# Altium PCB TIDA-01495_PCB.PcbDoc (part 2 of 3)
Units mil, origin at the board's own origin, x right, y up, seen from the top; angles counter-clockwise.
Board outline 7283.46 x 4330.71 mil, 2 copper layers (Top Layer, Bottom Layer), stack 64.6 mil thick; 242 components, 114 nets, 539 pads, 127 vias.
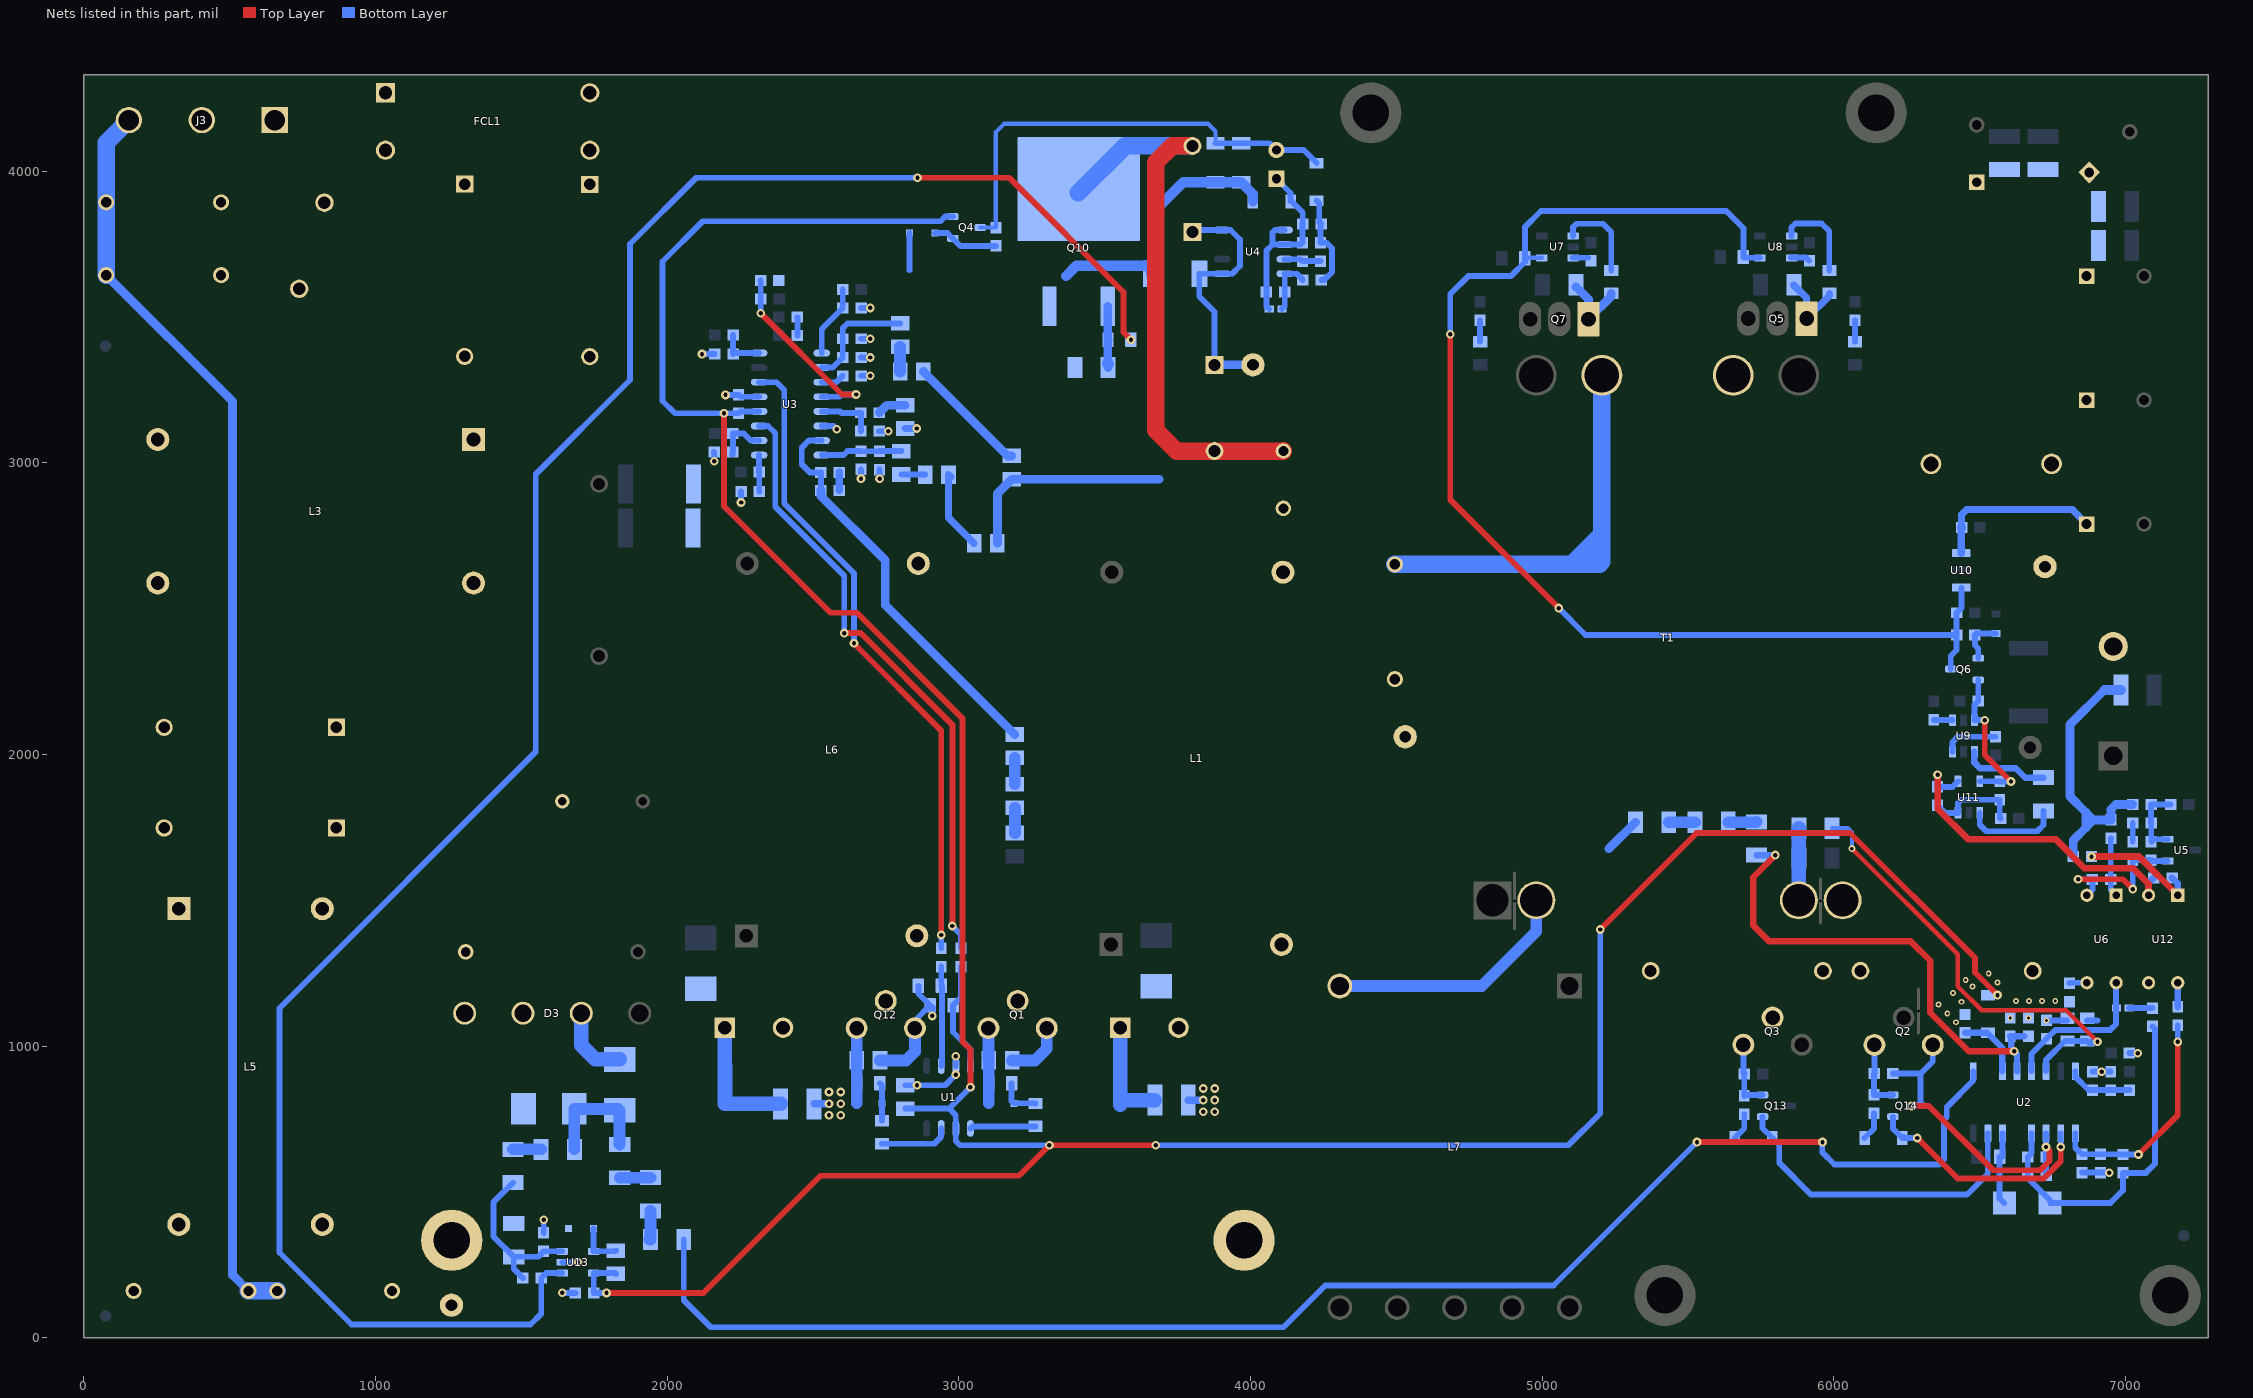
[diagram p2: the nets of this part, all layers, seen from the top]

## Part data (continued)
C41: "CAP, CERM, 1000 pF, 100 V, +/- 20%, X7R, 0603", Cap_Case=0603, Manufacturer=AVX, Supplier Part Number 1=478-3699-1-ND, TempCo=X7R, Tolerance_%=20, Value1="0.276 ohm", Value2=100V, ValueDisplayed=1000pF
C42: "CAP, CERM, 0.047 µF, 16 V,+/- 10%, X7R, 0603", Cap_Case=0603, Manufacturer=MuRata, Supplier Part Number 1=490-1529-1-ND, TempCo=X7R, Tolerance_%=10, Value2=16V, ValueDisplayed=0.047µF
C43: "CAP, CERM, 680 pF, 50 V, +/- 10%, X7R, 0603", Cap_Case=0603, Manufacturer=MuRata, Supplier Part Number 1=490-1491-1-ND, TempCo=X7R, Tolerance_%=10, Value1=Unknown, Value2=50V, ValueDisplayed=680pF
C44 C45: "CAP, CERM, 330 pF, 100 V, +/- 5%, C0G/NP0, 0603", Cap_Case=0603, Manufacturer=MuRata, Supplier Part Number 1=490-1363-1-ND, TempCo=C0G/NP0, Tolerance_%=5, Value1=Unknown, Value2=100V, ValueDisplayed=330pF
C46 C48: "CAP, CERM, 1 µF, 25 V, +/- 10%, X7R, 0805", Cap_Case=0805, Manufacturer=Kemet, Supplier Part Number 1=399-8004-1-ND, TempCo=X7R, Tolerance_%=10, Value1=Unknown, Value2=25V, ValueDisplayed=1µF
C47 C49: "CAP, CERM, 2200 pF, X1 250 VAC/Y2 300 VAC, +/- 20%, E, Radial D8x5mm", Cap_Case=CAPRD500W60D800H850, Manufacturer=MuRata, Supplier Part Number 1=490-4231-ND, TempCo=E, Tolerance_%=20, ValueDisplayed=2200pF
C50: "CAP, CERM, 10 pF, 50 V,+/- 5%, C0G/NP0, 0603", Cap_Case=0603, Manufacturer=AVX, Supplier Part Number 1=478-1163-1-ND, TempCo=C0G/NP0, Tolerance_%=5, Value1="0.403 ohm", Value2=50V, ValueDisplayed=10pF
C53 C54: "CAP, CERM, 2.2 µF, 16 V, +/- 10%, X6S, 0603", Cap_Case=0603, Manufacturer=TDK, Supplier Part Number 1=445-7438-1-ND, TempCo=X6S, Tolerance_%=10, Value1="0.007674 ohm", Value2=16V, ValueDisplayed=2.2µF
C55: "CAP, CERM, 0.01 µF, 630 V,+/- 10%, X7R, 1808", Cap_Case=1808, Manufacturer=Vishay-Vitramon, Supplier Part Number 1=720-1079-1-ND, TempCo=X7R, Tolerance_%=10, Value2=630V, ValueDisplayed=0.01µF
C56 C57: "CAP, CERM, 22 µF, 35 V,+/- 20%, X5R, 1206", Cap_Case=1206, Manufacturer=TDK, Supplier Part Number 1=445-8045-1-ND, TempCo=X5R, Tolerance_%=20, Value1="0.002398 ohm", Value2=35V, ValueDisplayed=22µF
C58 C59: "CAP, CERM, 100 pF, 50 V,+/- 5%, C0G/NP0, 0805", Cap_Case=0805, Manufacturer=AVX, Supplier Part Number 1=478-1316-1-ND, TempCo=C0G/NP0, Tolerance_%=5, Value1="0.356 ohm", Value2=50V, ValueDisplayed=100pF
C66 C67 C68 C72 C73: "CAP, CERM, 4.7 µF, 100 V, +/- 10%, X7S, 1210", Cap_Case=1210, Manufacturer=TDK, Supplier Part Number 1=445-8912-1-ND, TempCo=X7S, Tolerance_%=10, Value1=Unknown, Value2=100V, ValueDisplayed=4.7µF
D1 D5: "Diode, Ultrafast, 600V, 8A, TH", Manufacturer="ON Semiconductor", Supplier Part Number 1=MUR860GOS-ND, Value1=8A, Value2=600V
D2 D6: "Diode, Schottky, 30V, 0.2A, SOD-323", Manufacturer="ON Semiconductor", Supplier Part Number 1=BAT54HT1OSCT-ND, Value1=0.2A, Value2=30V
D3: library part GBU4A-BP, "DIODE GPP 8A 600V GPP INLINE GBU", Manufacturer=Vishay, Value1=4A, Value2=50V
D4 D19: library part CMP-0076889-1, "Diode, P-N, 1000 V, 1 A, SMB", Manufacturer="Diodes Inc.", Supplier Part Number 1=RS1MB-FDICT-ND, Value1=1A, Value2=1.3V
D7 D8 D11: "Diode, Schottky, 30 V, 0.35 A, SOD-123", Manufacturer="Diodes Inc.", Supplier Part Number 1=SD103-BWDICT-ND, Value1=0.35A, Value2=0.55V
D9 D10: "Diode, P-N, 1000 V, 1 A, SMB", Manufacturer="Diodes Inc.", Supplier Part Number 1=RS1MB-FDICT-ND, Value1=1A, Value2=1.3V
D12: "Diode, Zener, 6.2 V, 300 mW, SOD-523", Manufacturer="Diodes Inc.", Power_W=0.3, Supplier Part Number 1=BZT52C6V2T-7DICT-ND, Value1=0.3W
D13 D15: "Diode, Ultrafast, 600 V, 1 A, SOD-123FL", Manufacturer="Micro Commercial Components", Supplier Part Number 1=UFM15PL-TPMSCT-ND, Value1=1A, Value2=1.7V
D14: library part MM5Z5V6ST1G, "Diode, Zener, 5.61 V, 500 mW, SOD-523", Manufacturer="ON Semiconductor", Power_W=0.5, Supplier Part Number 1=MM5Z5V6ST1GOSCT-ND, Value1=0.5W
D16: "Diode, Zener, 15 V, 300 mW, SOD-323", Manufacturer="NXP Semiconductor", Power_W=0.3, Supplier Part Number 1=568-6280-1-ND, Value1=0.3W
D17: library part CMP-0005912-1, "Diode, Zener, 5.6 V, 150 mW, SOD-523F", Manufacturer="Comchip Technology", Power_W=150mW, Supplier Part Number 1=641-1030-1-ND, Value1=0.15W
D18: "Diode, Ultrafast, 600 V, 1 A, SMA", Manufacturer="Diodes Inc.", Supplier Part Number 1=US1J-FDICT-ND, Value1=1A, Value2=1.7V
D20: library part CMP-0005865-1, "Diode, Zener, 5.1 V, 200 mW, SOD-323", Manufacturer="Diodes Inc.", Power_W=200mW, Supplier Part Number 1=BZT52C5V1S-FDICT-ND, Value1=0.2W
FCL1: "FUSE CLIP, CARTRIDGE, 250V, 10A, PCB", Manufacturer=LITTELFUSE, Supplier Part Number 1=F4189-ND
FID1 FID2 FID3: "Fiducial mark.  There is nothing to buy or mount.", Manufacturer=N/A
H1 H2 H3 H4 H5 H6: "Bumpon, Hemisphere, 0.44 X 0.20, Clear", Manufacturer=3M, Supplier Part Number 1=SJ5303-7-ND
HS1 HS3: "HEATSINK VERT MAX CLIP, BLACK, 4.25 INCHES", Manufacturer=Aavid, Supplier Part Number 1=782653B04250G-ND
HS2: library part ATS-TI1OP-519-C1-R3, "Heat Sink, Vertical", Manufacturer="Advanced Thermal Solutions"
J2: "Terminal Block, 30A, 9.52mm (.375) Pitch, 2-Pos, TH", Manufacturer="On-Shore Technology", Supplier Part Number 1=ED2677-ND
J3: "Header(Shrouded), 6.35mm, 3x1, Tin, TH", Manufacturer="TE Connectivity", Supplier Part Number 1=A1468-ND
L1 L6: library part PFC4124QM-161K06D-00, "Transformer, 160 uH, TH"
L2: library part 7447020, "Inductor, Toroid, Powdered Iron, 150 µH, 5A, TH", Manufacturer="Wurth Elektronik", Supplier Part Number 1=732-1427-ND, Value1="0.16 ohm", Value2=5A, ValueDisplayed=150µH
L3 L5: "Coupled inductor, 3.3 mH, 5 A, 0.037 ohm, TH", Manufacturer="Wurth Elektronik", Supplier Part Number 1=732-3404-ND, ValueDisplayed=3.3mH
L4: "Inductor, Ferrite, 230 nH, 56 A, 0.0005 ohm, TH", Manufacturer="Delta Electronics Inc.", Value1="0.0005 ohm", Value2=56A, ValueDisplayed=230nH
L7: library part 1140-331K-RC, "Inductor, Ferrite, 330 µH, 6.1 A, 0.074 ohm, TH"
L8: library part 7447462102, "FIXED IND 2.2MH 210MA 11 OHM TH", Manufacturer="Wurth Elektronik", Supplier Part Number 1=732-3735-ND, Value1="4.38 ohm", Value2=0.25A, ValueDisplayed="2.2 mH"
Logo1: library part Pb-Free
Logo2: library part ESD_Susceptible, "ESD Susceptible Symbol"
LOGO3 LOGO9: library part IEC_HotSurface, "IEC 61010-1 Hot Surface Warning"
LOGO4 LOGO7 LOGO8 LOGO10: library part IEC_HighVoltage, "IEC 61010-1 High Voltage Warning"
Logo5: library part TI_Logo, "Texas Instrument Corporate Signature"
Logo6: library part FCC_disclaimer, "FCC_disclaimer"
Q1 Q12: "MOSFET, N-CH, 650 V, 20.2 A, TO-220AB", Alternate Manufacturer=None, Manufacturer="Infineon Technologies", Supplier Part Number 1=IPP60R190P6-ND, Value1="? ohm", Value2="37 nC"
Q2 Q3: library part IPP60R190P6, "MOSFET, N-CH, 650 V, 20.2 A, TO-220AB", Alternate Manufacturer=None, Manufacturer=STMicroelectronics, Supplier Part Number 1=497-13556-5-ND, Value1="? ohm", Value2="37 nC"
Q4: library part "BC848CLT1G, ON Semiconductor", "Transistor, NPN, 30 V, 0.1 A, SOT-23", Manufacturer="ON Semiconductor", Supplier Part Number 1=BC848CLT1GOSCT-ND, Value1="0.1 A", Value2=800
Q5 Q7: "MOSFET, N-CH, 100 V, 150 A, KCS0003B (TO-220-3)", Alternate Manufacturer=None, Manufacturer="Texas Instruments", Supplier Part Number 1=296-37289-5-ND, Value1="? ohm", Value2="118 nC"
Q6: library part CMP-0000421-2, "Transistor, NPN, 30 V, 0.6 A, SOT-23", Manufacturer="ON Semiconductor", Supplier Part Number 1=MMBT2222LT1GOSCT-ND, Value1="0.6 A", Value2=300
Q10: library part STB23NM50N, "MOSFET N CH 650V 35A D2PAK", Alternate Manufacturer=None, Manufacturer="ST Microelectronics", Supplier Part Number 1=497-12940-2-ND, Value1="? ohm", Value2="45 nC"
Q13 Q14: library part "BC858C-7-F, Diodes Inc.", "Transistor, PNP, 30 V, 0.1 A, SOT-23", Manufacturer="Diodes Inc.", Supplier Part Number 1=BC858C-7-F-ND, Value1="0.1 A", Value2=600
R1 R2 R13 R72: "RES, 10 k, 0.01%, 0.063 W, 0603", Manufacturer="Stackpole Electronics Inc", Power_W=0.063, Supplier Part Number 1=RNCF0603TKY10K0CT-ND, TempCo="5 ppm/C", Tolerance_%=0.01, Value1=0.01%, Value2=0.063W, Value_Code=10k0, ValueDisplayed=10k
R3: "RES, 162, 1%, 0.125 W, 0805", Manufacturer=Vishay-Dale, Power_W=0.125, Supplier Part Number 1=541-162CCT-ND, TempCo="100 ppm/C", Tolerance_%=1, Value1=1%, Value2=0.125W, Value_Code=162R, ValueDisplayed=162
R4 R5 R18: "RES, 18.2, 1%, 0.125 W, 0805", Manufacturer=Vishay-Dale, Power_W=0.125, Supplier Part Number 1=541-18.2CCT-ND, TempCo="100 ppm/C", Tolerance_%=1, Value1=1%, Value2=0.125W, Value_Code=18R2, ValueDisplayed=18.2
R6 R19 R74: "RES, 10.0 k, 1%, 0.125 W, 0805", Manufacturer=Vishay-Dale, Power_W=0.125, Supplier Part Number 1=541-10.0KCCT-ND, TempCo="100 ppm/C", Tolerance_%=1, Value1=1%, Value2=0.125W, Value_Code=10k0, ValueDisplayed=10.0k
R7 R8: "RES, 0.03, 1%, 2 W, 2512", Manufacturer="Stackpole Electronics Inc", Power_W=2, Supplier Part Number 1=CSRN2512FK30L0CT-ND, TempCo="200 ppm/C", Tolerance_%=1, Value1=1%, Value2=2W, Value_Code=R030, ValueDisplayed=0.03
R9: "RES, 70.6 k, 0.5%, 0.1 W, 0603", Manufacturer="Yageo America", Power_W=0.1, TempCo="50 ppm/C", Tolerance_%=0.5, Value1=0.5%, Value2=0.1W, Value_Code=70k6, ValueDisplayed=70.6k
R10 R22 R31: "RES, 1.00 k, 1%, 0.25 W, 1206", Manufacturer=Vishay-Dale, Power_W=0.25, Supplier Part Number 1=541-1.00KFCT-ND, TempCo="100 ppm/C", Tolerance_%=1, Value1=1%, Value2=0.25W, Value_Code=1k00, ValueDisplayed=1.00k
R11 R77: "RES, 511k ohm, 1%, 0.25W, 1206", Manufacturer=Vishay-Dale, Power_W=0.25, Supplier Part Number 1=541-511KFCT-ND, TempCo="100 ppm/C", Tolerance_%=1, Value1=1%, Value2=0.25W, Value_Code=511k
R12 R49 R66: "RES, 10.0 k, 1%, 0.1 W, 0603", Manufacturer=Vishay-Dale, Power_W=0.1, Supplier Part Number 1=541-10.0KHCT-ND, TempCo="100 ppm/C", Tolerance_%=1, Value1=1%, Value2=0.1W, Value_Code=10k0, ValueDisplayed=10.0k
R14 R76: "RES, 49.9k ohm, 1%, 0.25W, 1206", Manufacturer=Vishay-Dale, Power_W=0.25, Supplier Part Number 1=541-49.9KFCT-ND, TempCo="100 ppm/C", Tolerance_%=1, Value1=1%, Value2=0.25W, Value_Code=49k9
R15 R16: "RES, 2.2, 5%, 0.125 W, 0805", Manufacturer=Vishay-Dale, Power_W=0.125, Supplier Part Number 1=541-2.2ACT-ND, TempCo="200 ppm/C", Tolerance_%=5, Value1=5%, Value2=0.125W, Value_Code=2R20, ValueDisplayed=2.2
R17 R47 R71 R73: "RES, 6.04 k, 1%, 0.1 W, 0603", Manufacturer=Vishay-Dale, Power_W=0.1, Supplier Part Number 1=541-6.04KHCT-ND, TempCo="100 ppm/C", Tolerance_%=1, Value1=1%, Value2=0.1W, Value_Code=6k04, ValueDisplayed=6.04k
R20: "RES, 3.01 M, 1%, 0.125 W, 0805", Manufacturer=Vishay-Dale, Power_W=0.125, Supplier Part Number 1=541-3.01MCCT-ND, TempCo="100 ppm/C", Tolerance_%=1, Value1=1%, Value2=0.125W, Value_Code=3M01, ValueDisplayed=3.01M
R21 R23 R33: "RES, 2.87 M, 1%, 0.125 W, 0805", Manufacturer=Vishay-Dale, Power_W=0.125, Supplier Part Number 1=541-2.87MCCT-ND, TempCo="100 ppm/C", Tolerance_%=1, Value1=1%, Value2=0.125W, Value_Code=2M87, ValueDisplayed=2.87M
R24 R26: "RES, 16.5 k, 1%, 0.1 W, 0603", Manufacturer=Vishay-Dale, Power_W=0.1, Supplier Part Number 1=541-16.5KHCT-ND, TempCo="100 ppm/C", Tolerance_%=1, Value1=1%, Value2=0.1W, Value_Code=16k5, ValueDisplayed=16.5k
R25: "RES, 750 k, 1%, 0.1 W, 0603", Manufacturer=Vishay-Dale, Power_W=0.1, Supplier Part Number 1=541-750KHCT-ND, TempCo="100 ppm/C", Tolerance_%=1, Value1=1%, Value2=0.1W, Value_Code=750k
R27 R34 R46 R86 R87: "RES, 2.74 M, 1%, 0.125 W, 0805", Manufacturer=Vishay-Dale, Power_W=0.125, Supplier Part Number 1=541-2.74MCCT-ND, TempCo="100 ppm/C", Tolerance_%=1, Value1=1%, Value2=0.125W, Value_Code=2M74, ValueDisplayed=2.74M
R28: "RES, 2.2 k, 5%, 0.1 W, 0603", Manufacturer=Vishay-Dale, Power_W=0.1, Supplier Part Number 1=541-2.2KGCT-ND, TempCo="200 ppm/C", Tolerance_%=5, Value1=5%, Value2=0.1W, Value_Code=2k20, ValueDisplayed=2.2k
R29 R36 R69: "RES, 330 k, 5%, 0.25 W, 1206", Manufacturer=Vishay-Dale, Power_W=0.25, Supplier Part Number 1=541-330KECT-ND, TempCo="200 ppm/C", Tolerance_%=5, Value1=5%, Value2=0.25W, Value_Code=330k
R30: "RES, 100, 1%, 0.1 W, 0603", Manufacturer=Vishay-Dale, Power_W=0.1, Supplier Part Number 1=541-100HCT-ND, TempCo="100 ppm/C", Tolerance_%=1, Value1=1%, Value2=0.1W, Value_Code=100R, ValueDisplayed=100
R32 R70: "RES, 487 k, 1%, 0.1 W, 0603", Manufacturer=Vishay-Dale, Power_W=0.1, Supplier Part Number 1=541-487KHCT-ND, TempCo="100 ppm/C", Tolerance_%=1, Value1=1%, Value2=0.1W, Value_Code=487k
R35 R88: "RES, 133 k, 1%, 0.1 W, 0603", Manufacturer=Vishay-Dale, Power_W=0.1, Supplier Part Number 1=541-133KHCT-ND, TempCo="100 ppm/C", Tolerance_%=1, Value1=1%, Value2=0.1W, Value_Code=133k
R37 R39 R41 R51 R62: "RES, 100 k, 5%, 0.1 W, 0603", Manufacturer=Vishay-Dale, Power_W=0.1, Supplier Part Number 1=541-100KGCT-ND, TempCo="200 ppm/C", Tolerance_%=5, Value1=5%, Value2=0.1W, Value_Code=100k
R38 R40: "RES, 22, 5%, 0.1 W, 0603", Manufacturer=Vishay-Dale, Power_W=0.1, Supplier Part Number 1=541-22GCT-ND, TempCo="200 ppm/C", Tolerance_%=5, Value1=5%, Value2=0.1W, Value_Code=22R0, ValueDisplayed=22
R42: "RES, 7.50 k, 1%, 0.1 W, 0603", Manufacturer=Vishay-Dale, Power_W=0.1, Supplier Part Number 1=541-7.50KHCT-ND, TempCo="100 ppm/C", Tolerance_%=1, Value1=1%, Value2=0.1W, Value_Code=7k50, ValueDisplayed=7.50k
R43: "RES, 374 k, 1%, 0.25 W, 1206", Manufacturer=Vishay-Dale, Power_W=0.25, Supplier Part Number 1=541-374KFCT-ND, TempCo="100 ppm/C", Tolerance_%=1, Value1=1%, Value2=0.25W, Value_Code=374k
R44 R45: "RES, 4.7 k, 5%, 0.1 W, 0603", Manufacturer=Bourns, Power_W=0.1, Supplier Part Number 1=CR0603-JW-472GLFCT-ND, TempCo="200 ppm/C", Tolerance_%=5, Value1=5%, Value2=0.1W, Value_Code=4k70, ValueDisplayed=4.7k
R48: "RES, 147 k, 1%, 0.1 W, 0603", Manufacturer=Vishay-Dale, Power_W=0.1, Supplier Part Number 1=541-147KHCT-ND, TempCo="100 ppm/C", Tolerance_%=1, Value1=1%, Value2=0.1W, Value_Code=147k
R50: "RES, 16.9 k, 1%, 0.1 W, 0603", Manufacturer=Vishay-Dale, Power_W=0.1, Supplier Part Number 1=541-16.9KHCT-ND, TempCo="100 ppm/C", Tolerance_%=1, Value1=1%, Value2=0.1W, Value_Code=16k9, ValueDisplayed=16.9k
R52 R53: "RES, 10, 5%, 0.125 W, 0805", Manufacturer=Vishay-Dale, Power_W=0.125, Supplier Part Number 1=541-10ACT-ND, TempCo="200 ppm/C", Tolerance_%=5, Value1=5%, Value2=0.125W, Value_Code=10R0, ValueDisplayed=10
R54 R57: library part CMP-0018338-2, "RES, 4.70 k, 1%, 0.25 W, 1206", Manufacturer="Yageo America", Power_W=250mW, Supplier Part Number 1=311-4.70KFRCT-ND, TempCo="100 ppm/C", Tolerance_%=1%, Value2=0.25W, Value_Code=4k70, ValueDisplayed=4.70k
R55: "RES, 12 k, 5%, 0.1 W, 0603", Manufacturer=Vishay-Dale, Power_W=0.1, Supplier Part Number 1=541-12KGCT-ND, TempCo="200 ppm/C", Tolerance_%=5, Value1=5%, Value2=0.1W, Value_Code=12k0, ValueDisplayed=12k
R56: "RES, 47.0 k, 0.1%, 0.1 W, 0603", Manufacturer="Yageo America", Power_W=0.1, TempCo="25 ppm/C", Value1=0.1%, Value2=0.1W, Value_Code=47k0, ValueDisplayed=47.0k
R58 R59: "RES, 10.0, 1%, 0.25 W, 0603", Manufacturer=Vishay-Dale, Power_W=0.25, Supplier Part Number 1=541-10.0SCT-ND, TempCo="100 ppm/C", Tolerance_%=1, Value1=1%, Value2=0.25W, Value_Code=10R0, ValueDisplayed=10.0
R60 R61: "RES, 4.7, 5%, 0.125 W, 0805", Manufacturer=Vishay-Dale, Power_W=0.125, Supplier Part Number 1=541-4.7ACT-ND, TempCo="200 ppm/C", Tolerance_%=5, Value1=5%, Value2=0.125W, Value_Code=4R70, ValueDisplayed=4.7
R63 R64: library part CMP-0022751-4, "RES, 10.0, 1%, 0.1 W, 0603", Manufacturer=Yageo, Power_W=100mW, Supplier Part Number 1=311-10.0HRCT-ND, TempCo="100 ppm/C", Tolerance_%=1%, Value2=0.1W, Value_Code=10R0, ValueDisplayed=10.0
R65: library part CMP-0015817-2, "RES, 0.001, 1%, 1 W, 2512", Manufacturer=Panasonic, Power_W=1W, Supplier Part Number 1=P1.0NDCT-ND, TempCo=ppm/C, Tolerance_%=1%, Value_Code=1L000, ValueDisplayed=0.001
R67 R68: library part CMP-0022731-2, "RES, 1.00 M, 1%, 0.125 W, 0603", Manufacturer=Vishay/Beyschlag, Power_W=125mW, Supplier Part Number 1=MCT0603-1.00M-CFCT-ND, TempCo="50 ppm/C", Tolerance_%=1%, Value2=0.125W, Value_Code=1M00, ValueDisplayed=1.00M
R75: library part CMP-0022142-4, "RES, 1.10 M, 1%, 0.1 W, AEC-Q200 Grade 0, 0603", Manufacturer=Vishay-Dale, Power_W=100mW, Supplier Part Number 1=541-1.10MHCT-ND, TempCo="100 ppm/C", Tolerance_%=1%, Value2=0.1W, Value_Code=1M10, ValueDisplayed=1.10M
R89: "RES, 66.5 k, 1%, 0.1 W, 0603", Manufacturer=Vishay-Dale, Power_W=0.1, Supplier Part Number 1=541-66.5KHCT-ND, TempCo="100 ppm/C", Tolerance_%=1, Value1=1%, Value2=0.1W, Value_Code=66k5, ValueDisplayed=66.5k
R90: "RES, 82.5 k, 1%, 0.1 W, 0603", Manufacturer=Vishay-Dale, Power_W=0.1, Supplier Part Number 1=541-82.5KHCT-ND, TempCo="100 ppm/C", Tolerance_%=1, Value1=1%, Value2=0.1W, Value_Code=82k5, ValueDisplayed=82.5k
RT1: "Thermistor NTC, 10 ohm, 20%, Disc_11.5mmx6mm", Manufacturer="EPCOS Inc", Power_W=2.1, Supplier Part Number 1=495-2094-ND, Tolerance_%=20
RV1: "Varistor 275V RMS 10MM Radial, TH", Manufacturer="EPCOS Inc", Supplier Part Number 1=495-1433-ND
T1: "Transformer, TH", Manufacturer=Payton
TP1 TP3 TP6: "Test Point, Miniature, Black, TH", Manufacturer=Keystone, Supplier Part Number 1=5001K-ND
TP2 TP5: "Test Point, Miniature, Red, TH", Manufacturer=Keystone, Supplier Part Number 1=5000K-ND
U1: "Dual 5-A High-Speed Low-Side Gate Driver, D0008A", Alternate Manufacturer="Texas Instruments"
U2: "Enhanced LLC Resonant Controller with Driver, DDB0014A (SOIC-14)", Alternate Manufacturer="Texas Instruments"
U3: "Natural Interleaving™ Transition-Mode PFC Controller with Improved Audible Noise Immunity, D0016A", Alternate Manufacturer="Texas Instruments", Alternate PartNumber=UCC28063D
U4: "700-V Lowest Quiescent Current Off-Line Switcher, D0007A", Alternate Manufacturer="Texas Instruments"
U5: "Adjustable Precision Shunt Regulator, 34 ppm / degC, 100 mA, 0 to 70 degC, 3-pin SOT-23 (DBZ), Green (RoHS & no Sb/Br)", Alternate Manufacturer="Texas Instruments", Alternate PartNumber=Equivalent, Rating=Catalog, Supplier Part Number 1=296-17328-2-ND, Temp Coeff(Typ)(ppm/ degree C)=34
U6 U12: "Optocoupler, 5.3 kV, 50-600% CTR, TH", Manufacturer=Vishay-Semiconductor, Supplier Part Number 1=VO618A-ND, Voltage_Isolation_Vrms=5300V
U7 U8: "UCC24612-1DBV, DBV0005A (SOT-23-5)", Alternate Manufacturer="Texas Instruments", Alternate PartNumber=UCC24612-1DBVT
U9: library part CMP-0013234-2, "Bidirectional, Low- and High-Side Measurement, Multichannel, Voltage Output, Current-Sense Amplifier, DBV0006A (SOT-6)", Alternate Manufacturer="Texas Instruments"
U10: library part CMP-0074738-2, "3 Pin 100mA Fixed 5V Positive Voltage Regulator, PK0003A (SOT-3)", Alternate Manufacturer="Texas Instruments"
U11: library part CMP-0065409-1, "SINGLE DIFFERENTIAL COMPARATOR, DBV0005A (SOT-23-5)", Alternate Manufacturer="Texas Instruments", Alternate PartNumber=TL331IDBVT
U13: library part CMP-0073526-1, "36V, Low-Power, RRO, General-Purpose Operational Amplifier, DBV0005A (SOT-23-5)", Alternate Manufacturer="Texas Instruments", Alternate PartNumber=TLV171IDBVT
ZZ1: library part AssemblyNoteLabel, Alternate Manufacturer=-
ZZ2 ZZ3 ZZ4: library part AssemblyNote, Alternate Manufacturer=-

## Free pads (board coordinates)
  oval 10x200 hole 10 slot 200 at 90 deg unplated mask+5: 6(4905,1498)
  oval 10x160 hole 10 slot 160 at 90 deg unplated mask+5: 6(5955,1498) 6(6290,1120)

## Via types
v1: diameter 30, hole 15, Top Layer to Bottom Layer, 109 vias
v2: diameter 20, hole 10, Top Layer to Bottom Layer, 16 vias
v3: diameter 24, hole 12, Top Layer to Bottom Layer, 2 vias

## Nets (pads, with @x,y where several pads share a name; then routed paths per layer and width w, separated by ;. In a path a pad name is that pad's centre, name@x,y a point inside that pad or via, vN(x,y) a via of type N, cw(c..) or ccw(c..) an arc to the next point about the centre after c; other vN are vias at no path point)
12V: C32.1 C35.1 D18.2 R13.1 R25.2 U2.12 | length 1201.3
  Bottom Layer w20: U2.12@6677.97,701.33 6677.97,633.13 C32.1@6664.85,620.01 6664.85,557.09 C35.1@6664.94,556.99 6664.94,547.73 6741.87,470.8 D18.2@6741.87,461.95 6948.15,461.95 6991,504.81 R25.2@6991,565.5 7069.74,565.5 7101,596.76 7101,1059.5 R13.1@7093,1067.5
24V: C60.1 C66.1 C76.1 C77.1 J2.2 L4.2 R17.2 R48.2 R71.2 TP5.1 U10.3 | length 1556.2
  Bottom Layer w25: U10.3@6437.27,2689.89 C60.1@6437.27,2777.35 ; C60.1@6437.76,2777.84 6437.76,2821.42 6456,2839.65 6816.92,2839.65 C77.1@6866.57,2790
  Bottom Layer w30: C60.1@6437.27,2777.35 C60.1@6437.76,2777.84 ; R71.2@6820.42,1649.82 6820.42,1705.44 6864.81,1749.83 ; 6928.17,2221 6809.36,2102.19 6809.36,1856.61 6864.81,1801.16 ; R48.2@7024.49,1828.6 6966.44,1828.6 6950,1812.16 R17.2@6950,1775.5 6890.48,1775.5 ; 6864.81,1749.83 6890.48,1775.5 ; 6864.81,1749.83 6864.81,1801.16 ; 6864.81,1801.16 6890.48,1775.5
  Bottom Layer w35: 6928.17,2221 C66.1@6983.91,2221
390V: C1.1 C2.1 C15.1 C55.1 C69.1 C70.1 D1.1 D4.1 D5.1 D19.1 Q3.2 R20.2 R43.2 R87.2 TP2.1 U4.5 U4.8 | length 2598.2
  Bottom Layer w20: C1.1@3801.29,3790.73 3808.56,3798 U4.8@3902.72,3798 3931.43,3798 3963.82,3765.61 3963.82,3674.31 3937.51,3648 U4.5@3902.72,3648 C55.1@3824.68,3648 ; C55.1@3824.68,3645.27 3824.68,3570.01 3877,3517.68 C70.1@3877,3335.58
  Bottom Layer w30: R87.2@3132.4,2724.21 3132.4,2894.11 R20.2@3181.79,2943.49 3687.53,2943.49 ; C70.1@3877,3335.58 3877.06,3335.64 TP2.1@4008.63,3335.64 ; 5228.58,1676.67 R43.2@5319.91,1768
  Bottom Layer w50: D5.1@2197.66,1063.35 2198.33,1062.69 2198.33,933.88 2198.48,933.73 2198.48,802.49 C69.1@2389.48,802.49 ; D1.1@3553.7,1063.35 3553.91,1063.14 3553.91,800 3568.48,814.56 C15.1@3672.47,814.56
AUX_15V: C7.1 C23.1 C30.1 D11.2 Q4.2 R74.2 U1.6 U3.12 U13.5 | length 11543.1
  Top Layer w20: v1(1792.41,154) 2124.39,154 2526.07,555.68 3206.37,555.68 v1(3310.75,660.06) v1(3310.75,660.06) v1(3675,660) ; v1(2195.03,3169.64) 2195.03,2851.1 2560.5,2485.64 2650.88,2485.64 3012.35,2124.18 3012.35,1016.1 3040,988.45 v1(3040,859) ; v1(5199,1400) 5529.66,1730.66 6055.59,1730.66 6483.64,1302.61 6483.64,1252.36 v1(6561,1175)
  Bottom Layer w20: v1(1792.41,154) C7.1@1748.5,154 1748.74,154.25 U13.5@1748.74,221.83 1822.01,221.83 R74.2@1824.61,219.23 ; U3.12@2315.54,3176.17 2251.95,3176.17 C30.1@2245.41,3169.64 v1(2195.03,3169.64) 2026.86,3169.64 1984.35,3212.16 1984.35,3689.83 2122.41,3827.89 2937.16,3827.89 2953.27,3843.99 Q4.2@2979.71,3843.99 ; C23.1@2816.34,785.95 2967.02,785.95 ; v1(3040,859) 3040,858.93 2967.02,785.95 ; v1(3310.75,660.06) 3310.35,660.47 3004.07,660.47 2989.94,674.6 U1.6@2989.94,717.9 2989.94,763.03 2967.02,785.95 ; v1(3675,660) 5089.63,660 5199,769.37 v1(5199,1400)
BLK: C17.2 R2.2 R29.1 U2.4 | length 1690.9
  Top Layer w22: v1(5799.3,1654.91) 5723.68,1579.3 5723.68,1413.9 5777.53,1360.05 6263.09,1360.05 6330.33,1292.81 6330.33,1114.55 6462.73,982.15 v1(6618.04,982.15)
  Bottom Layer w22: R29.1@5735,1654.91 v1(5799.3,1654.91) ; R2.2@6605,1033.5 R2.2@6605.11,1033.39 ; U2.4@6627.97,913.93 6627.97,972.23 v1(6618.04,982.15) 6607.67,992.53 6607.67,1030.84 R2.2@6605.11,1033.39 ; C17.2@6652.69,1033.39 R2.2@6605.11,1033.39
BW: C20.1 R9.1 R12.2 U2.8 | length 223.9
  Bottom Layer w20: U2.8@6827.97,913.93 6827.97,894.94 6873.36,849.55 C20.1@6886.38,849.55 R12.2@6949.52,849.55 R9.1@7014.06,849.55
COMP: C34.1 R42.1 U3.5 | length 200.1
  Bottom Layer w20: U3.5@2530.1,3176.17 2592.28,3176.17 2597.99,3170.46 2663.37,3170.46 R42.1@2664.28,3171.38 2664.28,3108.69 C34.1@2663.92,3108.33
DRV: R5.2 R75.2 U13.1 | length 7294.6
  Top Layer w20: v1(2858.72,3977.33) 3172.63,3977.33 3564.35,3585.61 3564.35,3448.02 v1(3590.37,3422)
  Bottom Layer w20: U13.1@1640.48,221.83 1585.56,221.83 R75.2@1568.61,204.88 1568.61,82.09 1532,45.48 917.77,45.48 670.9,292.36 670.9,1129.85 1549.96,2008.9 1549.96,2960.44 1873.01,3283.48 1873.01,3750.12 2100.21,3977.33 v1(2858.72,3977.33)
EARTH: C6.2 C11.1 C47.2 C49.1 J3.3 | length 4348.4
  Top Layer w50: C47.2@663.82,160.67 C47.2@664.15,161
  Bottom Layer w30: C11.1@77.15,3643.15 510.43,3209.88 510.43,215.22 C49.1@564.97,160.67
  Bottom Layer w60: C11.1@77.15,3643.15 C6.2@77.15,3893 77.15,4097.15 J3.3@155,4175 ; C49.1@564.97,160.67 565.3,161 C47.2@664.15,161
G1: R61.1 U7.1 | length 309.4
  Bottom Layer w20: U7.1@5106.37,3777.47 5106.37,3808.21 5117.56,3819.41 5208.28,3819.41 5236.84,3790.84 R61.1@5236.84,3659.15
G2: R60.2 U8.1 | length 309.6
  Bottom Layer w20: U8.1@5855.13,3777.4 5855.13,3807 5868.56,3820.43 5958,3820.43 5984.15,3794.28 R60.2@5984.15,3659.68
GD1: R58.1 U3.14 | length 2234.2
  Top Layer w20: v1(2641,2381) 2641,2380.71 2940,2081.71 v1(2940,1381)
  Bottom Layer w20: U3.14@2315.54,3276.17 2375.01,3276.17 2401.74,3249.44 2401.74,2860.46 2641,2621.2 v1(2641,2381) ; R58.1@2940,1335.5 v1(2940,1381)
GD2: R59.1 U3.11 | length 2128.3
  Top Layer w20: v1(2607.55,2416.15) 2663.57,2416.15 2978,2101.72 v1(2978,1412)
  Bottom Layer w20: U3.11@2315.54,3126.17 2346.3,3126.17 2370.64,3101.83 2370.64,2849.13 2607.55,2612.22 v1(2607.55,2416.15) ; v1(2978,1412) 3008,1382 R59.1@3008,1335.5
HO: D7.2 Q13.1 U2.15 | length 1111
  Bottom Layer w20: Q13.1@5755.69,758.17 5755.69,718.78 D7.2@5789.47,685 5812.92,661.55 5812.92,599.93 5921.96,490.88 6456.92,490.88 6527.97,561.93 U2.15@6527.97,701.33
I_OUT: R69.2 U9.1 | length 295.3
  Bottom Layer w22: U9.1@6482.13,2009.36 6482.13,1972.23 6501.14,1953.22 6623.45,1953.22 6656.16,1920.51 R69.2@6718.84,1920.51
ISNS: C19.1 C39.2 R3.2 U2.6 | length 1560.9
  Top Layer w15: v3(6062.22,1677.55) 6072.07,1667.7 6424.99,1314.79 6424.99,1204.84 6506.89,1122.93 6796.07,1122.93 v1(6904,1015)
  Bottom Layer w15: C39.2@5994.36,1747 6048.08,1747 6062.22,1732.86 v3(6062.22,1677.55)
  Bottom Layer w20: U2.6@6727.97,913.93 6727.97,953.09 6792.5,1017.63 C19.1@6801,1017.63 6867.92,1017.63 6876.55,1009 6884.55,1017 6888.55,1013 6890.55,1015 v1(6904,1015)
ISO_5V: C62.1 Q6.2 R68.2 U9.6 U11.5 | length 533.4
  Top Layer w20: v1(6517.29,2117.63) 6517.29,1997.8 v1(6607.6,1907.5)
  Bottom Layer w20: Q6.2@6495.21,2255.37 6495.21,2183.75 C62.1@6495.03,2183.57 6482.13,2170.67 U9.6@6482.13,2117.63 v1(6517.29,2117.63) ; U11.5@6500.22,1907.9 6568.59,1907.9 R68.2@6569,1907.5 v1(6607.6,1907.5)
ISO_15V: C46.1 C48.1 C61.1 Q6.3 R66.1 U7.4 U8.4 U10.1 | length 4358.6
  Top Layer w20: v1(4685.18,3440.48) 4685.18,2873.46 v1(5056.8,2501.84)
  Bottom Layer w15: C46.1@4942.86,3702.66 U7.4@4998.1,3702.66
  Bottom Layer w20: v1(4685.18,3440.48) 4685.18,3578.31 4746.75,3639.88 4892.51,3639.88 4942.86,3690.22 C46.1@4942.86,3702.66 ; C46.1@4940.77,3700.57 4940.77,3807.68 4995.87,3862.78 5631.17,3862.78 5690.09,3803.87 C48.1@5690.09,3705.36 5692.86,3702.6 U8.4@5746.87,3702.6 ; v1(5056.8,2501.84) 5149.02,2409.62 R66.1@6420.88,2409.62 ; Q6.3@6400.72,2292.77 6400.72,2337.74 6420.88,2357.9 R66.1@6420.88,2409.62 ; U10.1@6437.27,2571.78 6437.27,2502.12 C61.1@6420.88,2485.72 R66.1@6420.88,2409.62
LL/SS: C31.1 R25.1 R32.2 R70.2 U2.9 | length 775.6
  Top Layer w20: v1(7044.21,628.5) 7178.95,763.24 v1(7178.95,1014.52)
  Bottom Layer w20: U2.9@6827.97,701.33 6827.97,651.77 C31.1@6850.46,629.27 R32.2@6914.46,629.27 6990.23,629.27 R25.1@6991,628.5 ; R25.1@6989.46,628.5 R25.1@6991,628.5 ; v1(7044.21,628.5) R25.1@6991,628.5 ; v1(7178.95,1014.52) R70.2@7178.95,1071.32
LO: D8.2 Q14.1 U2.10 | length 812.2
  Top Layer w20: v1(6286,685) 6424.46,546.54 6719.48,546.54 6777.97,605.03 v1(6777.97,654.28)
  Bottom Layer w20: Q14.1@6202.78,758.17 6202.78,716.68 D8.2@6234.47,685 6238.98,689.52 6244.5,684 6245.5,685 v1(6286,685) ; v1(6777.97,654.28) U2.10@6777.97,701.33
NETA: D9.1 D10.1 R11.1 R31.1 | length 413.6
  Bottom Layer w40: R11.1@1682.09,646 1681.68,646.4 D9.1@1681.68,784.65 1832.68,784.65 D10.1@1836.97,780.35 1836.97,664.12 R31.1@1838,663.09
NetC1_2: C1.2 C70.2 Q10.4 RT1.2 | length 1992.8
  Top Layer w60: C1.2@3801.29,4086.01 3731.27,4086.01 3675.7,4030.45 3675.7,3111.53 3746.93,3040.3 C70.2@3877,3040.3 4112.88,3040.3 RT1.2@4113,3040.43
  Bottom Layer w60: Q10.4@3409.45,3925.33 3570.12,4086.01 C1.2@3801.29,4086.01
NetC2_2: C2.2 C3.1 C39.1 C40.1 T1.6 | length 247.1
  Bottom Layer w50: T1.6@5880,1500 5880.19,1500.19 C40.1@5880.19,1645.3 C39.1@5880.19,1747
NetC4_1: C4.1 D3.1 L2.1
NetC6_1: C6.1 C9.1 C52.1 FCL1.3 FCL1.4 L3.1 RV1.2 | length 3.9
  Top Layer w50: RV1.2@823.94,3893 RV1.2@825.31,3891.64 ; C52.1@1306,3955.28 C52.1@1307,3954.28 ; FCL1.4@1735,4071.18 FCL1.4@1735.39,4071.57
NetC8_1: C8.1 C12.1 C13.1 C14.1 C67.1 C68.1 C72.1 C73.1 L4.1 T1.10 T1.11 | length 1479.3
  Bottom Layer w60: C8.1@4495,2651.85 5196.97,2651.85 5205,2659.88 5205,2754.99 ; 5101.86,2651.85 5205,2754.99 ; T1.11@5205,3280 5205,2754.99
NetC9_2: C9.2 C11.2 C52.2 J3.2 L3.4 RV1.1
NetC10_1: C10.1 C51.1 L3.2 L5.4
NetC10_2: C10.2 C51.2 L3.3 L5.1
NetC16_1: C16.1 D11.1 U2.3 | length 229.4
  Bottom Layer w22: C16.1@6450,1045.5 6526.53,1045.53 6577.97,994.09 U2.3@6577.97,913.93
NetC18_1: C18.1 D12.2 U2.5 U6.4 | length 533.1
  Bottom Layer w20: U2.5@6677.97,913.93 6677.97,973.46 C18.1@6729.53,1025.02 6755.13,1050.63 6755.56,1050.63 6760.81,1055.88 6947.56,1055.88 6967.88,1076.2 U6.4@6967.88,1217.31
NetC21_1: C21.1 R75.1 R76.2 R77.2 U13.3 | length 571.1
  Bottom Layer w20: R77.2@1472,531.91 1404.47,464.38 1404.47,347.47 R76.2@1474.12,277.81 ; R75.1@1505.61,204.88 1474.12,236.37 R76.2@1474.12,277.81 ; U13.3@1640.48,296.64 1577.13,296.64 C21.1@1577,296.5 1558.31,277.81 R76.2@1474.12,277.81
NetC24_1: C24.1 R24.2 U3.16 | length 149.7
  Bottom Layer w20: C24.1@2226.43,3372.69 2226.43,3437.72 R24.2@2226.66,3437.96 ; C24.1@2231.2,3376.17 U3.16@2315.54,3376.17
NetC25_1: C25.1 R26.1 U3.1 | length 247.6
  Bottom Layer w20: U3.1@2530.1,3376.17 2530.1,3458.8 C25.1@2602.23,3530.93 R26.1@2602.23,3593.93
NetC26_1: C26.1 D18.1 U2.14 | length 245.9
  Bottom Layer w20: C26.1@6568.37,621 6568.37,477.98 D18.1@6584.39,461.95 ; C26.1@6577.97,621.12 U2.14@6577.97,701.33
NetC27_1: C27.1 D14.1 R28.1 U4.4 | length 196.1
  Bottom Layer w20: D14.1@4107.65,3527 4117.5,3536.84 C27.1@4117.5,3585 4117.5,3647.79 U4.4@4117.28,3648 4158.5,3648 R28.1@4179.5,3627
NetC27_2: C27.2 C28.2 D14.2 D15.1 L8.1 R55.1 U4.1 U4.2 | length 682.7
  Bottom Layer w20: D14.2@4064.35,3527 4054.5,3536.84 C27.2@4054.5,3585 4054.5,3726.95 4075.55,3748 ; L8.1@4089,3973.79 4137.58,3925.21 D15.1@4137.58,3896.42 ; U4.1@4117.28,3798 4084.63,3798 4075.55,3788.93 4075.55,3748 ; D15.1@4139.83,3897.3 4179.5,3857.63 C28.2@4179.5,3819 4178,3817.5 R55.1@4178,3754.5 4171.5,3748 U4.2@4117.28,3748 4075.55,3748
NetC28_1: C28.1 D13.1 R28.2 R51.1 | length 329.2
  Bottom Layer w20: D13.1@4227.09,3898.52 4235.7,3889.91 4235.7,3825.79 C28.1@4242.5,3819 4240,3816.5 R51.1@4240,3754.5 4260.36,3754.5 4279.74,3735.12 4279.74,3653.27 4253.47,3627 R28.2@4242.5,3627
NetC29_1: C29.1 R30.2 U3.10 | length 173.5
  Bottom Layer w20: C29.1@2224.61,3027.78 C29.1@2224.61,3036.39 2225.71,3037.49 R30.2@2225.71,3100.8 2262.19,3100.8 2286.82,3076.17 U3.10@2315.54,3076.17
NetC33_1: C33.1 R34.1 R35.2 U3.2 | length 390.4
  Bottom Layer w20: U3.2@2530.1,3326.17 2567.02,3326.17 2601.9,3361.06 C33.1@2602.32,3361.06 2602.32,3424.92 R35.2@2602.15,3425.09 2602.15,3461.41 2618.53,3477.79 R34.1@2798.66,3477.79
NetC36_1: C36.1 R42.2 | length 100
  Bottom Layer w30: R42.2@2727.27,3171.38 2753.52,3197.62 C36.1@2816.35,3197.62
NetC41_1: C41.1 R33.1 R88.2 U3.7 | length 1387.1
  Bottom Layer w20: C41.1@2527.59,2905.14 R88.2@2527.59,2967.14 2489.27,2967.14 2461.48,2994.93 2461.48,3051.57 2486.08,3076.17 U3.7@2530.1,3076.17
  Bottom Layer w30: C41.1@2527.59,2905.14 2527.59,2885.56 2747.83,2665.33 2747.83,2512.44 R33.1@3191.96,2068.31
NetC42_1: C42.1 R49.1 | length 64
  Bottom Layer w20: R49.1@7024.74,1765.04 7024.74,1701.35 C42.1@7024.99,1701.1
NetC42_2: C42.2 C50.2 R47.1 U5.1 U6.2 | length 533.8
  Top Layer w20: v1(6837.45,1572) 6991.42,1572 v1(7025,1538.42)
  Bottom Layer w20: v1(6837.45,1572) R47.1@6886.5,1572 6886.5,1535.93 U6.2@6867.88,1517.31 ; v1(7025,1538.42) C42.2@7024.99,1638.11 C50.2@7087.99,1638.11 7091.49,1634.6 U5.1@7144.76,1634.6
NetC43_1: C43.1 R46.1 R90.2 U3.8 | length 279.1
  Bottom Layer w20: U3.8@2530.1,3026.17 2604.68,3026.17 2618.54,3040.03 C43.1@2664.81,3040.03 2665.09,3039.75 R90.2@2728.62,3039.75 2728.72,3039.85 R46.1@2803.32,3039.85
NetC44_2: C44.2 R52.2 | length 73.6
  Bottom Layer w20: R52.2@6072.63,3414.85 C44.2@6072.63,3488.42
NetC45_2: C45.2 R53.2 | length 73.6
  Bottom Layer w20: R53.2@4787.51,3414.95 C45.2@4787.51,3488.52
NetC47_1: C47.1 D3.2 D9.2 L5.3
NetC49_2: C49.2 D3.3 D10.2 L5.2 | length 261.3
  Bottom Layer w50: D3.3@1706,1112.85 1706,1002.46 1754.1,954.37 D10.2@1836.97,954.37
NetC50_1: C50.1 R48.1 R49.2 R50.2 U5.2 | length 255.1
  Bottom Layer w20: U5.2@7144.76,1709.4 7096.29,1709.4 C50.1@7087.99,1701.1 7087.99,1764.79 R49.2@7087.73,1765.04 7087.73,1828.36 R48.1@7087.48,1828.6 7154.34,1828.6 R50.2@7154.57,1828.83
NetC53_1: C53.1 U7.3 | length 50.7
  Bottom Layer w20: U7.3@5106.37,3702.66 C53.1@5157.09,3702.66
NetC54_1: C54.1 U8.3 | length 65.6
  Bottom Layer w20: U8.3@5853.68,3703.19 5904.4,3703.19 C54.1@5914.92,3692.67
NetC56_1: C56.1 C57.1 D13.2 L8.2 Q4.3 R56.2 | length 1572
  Bottom Layer w15: Q4.3@3074.2,3806.59 3074.34,3806.46 R56.2@3127.24,3806.46 3127.24,4133.99 3155.08,4161.83 3855.33,4161.83 3880.32,4136.84 C57.1@3880.32,4095.36
  Bottom Layer w20: C57.1@3880.32,4095.36 C56.1@3968,4095.36 4065.85,4095.36 L8.2@4089,4072.21 4182.33,4072.21 D13.2@4227.09,4027.45
NetC58_1: C58.1 R58.2 U1.2 | length 341.8
  Bottom Layer w20: U1.2@2939.94,932.46 2942.1,934.62 2942.1,1205.27 C58.1@2940.37,1207 2940,1207.37 R58.2@2940,1272.5
NetC59_1: C59.1 R59.2 U1.4 | length 376.2
  Bottom Layer w20: R59.2@3008,1272.5 3008,1167.63 C59.1@2980.37,1140 2980.37,1048.46 3039.94,988.89 U1.4@3039.94,932.46
NetD1_3: D1.3 L1.2 Q1.2
NetD2_1: D2.1 R4.1 R15.2 | length 146.2
  Bottom Layer w20: R4.1@3181.37,873 3181.37,811.94 D2.1@3189.31,804 3262.37,804 R15.2@3263,803.37
NetD2_2: D2.2 Q1.1 R4.2 R6.2 | length 258.3
  Bottom Layer w40: Q1.1@3101.76,1061.85 3101.76,951.99 R6.2@3102.76,951 3102.76,873.13 R4.2@3102.63,873 3102.63,804.06 D2.2@3102.69,804
NetD5_3: D5.3 L6.2 Q12.2
NetD6_1: D6.1 R16.2 R18.1 | length 132
  Bottom Layer w20: R18.1@2729.37,873 2737.31,865.06 D6.1@2737.31,804 2737.31,744.68 R16.2@2737,744.37
NetD6_2: D6.2 Q12.1 R18.2 R19.2 | length 258.2
  Bottom Layer w40: Q12.1@2649.75,1061.85 2650,1061.6 R19.2@2650,951 2650.63,950.37 R18.2@2650.63,873 2650.69,872.94 D6.2@2650.69,804
NetD7_1: D7.1 R38.1 | length 94.9
  Bottom Layer w20: D7.1@5660.53,685 5692.93,717.4 R38.1@5692.93,766.48
NetD8_1: D8.1 R40.1 | length 98
  Bottom Layer w20: D8.1@6105.53,685 6137.78,717.25 R40.1@6137.78,769.61
NetD12_1: D12.1 R13.2 | length 80.7
  Bottom Layer w20: D12.1@7012.46,1130.97 7012.93,1130.5 R13.2@7093,1130.5
NetD16_1: D16.1 Q4.1 R56.1 | length 226.9
  Bottom Layer w20: D16.1@2918.8,3788.06 2960.84,3788.06 Q4.1@2979.71,3769.19 3005.44,3743.47 R56.1@3127.24,3743.47
NetD17_1: D17.1 Q6.1 R66.2 | length 158.1
  Bottom Layer w20: Q6.1@6495.21,2330.17 6495.21,2362.79 6483.87,2374.13 R66.2@6483.87,2409.62 6488.46,2414.2 D17.1@6555.94,2414.2
NetD20_1: D20.1 R74.1 U13.4 | length 155.5
  Bottom Layer w20: D20.1@1748.31,375 1748.31,297.07 U13.4@1748.74,296.64 1822.01,296.64 R74.1@1824.61,299.23
NetFCL1_1: FCL1.1 FCL1.2 J3.1
NetL7_2: L7.2 T1.2 | length 858
  Bottom Layer w40: L7.2@4306.3,1206.18 4793.05,1206.18 4980,1393.13 T1.2@4980,1500
NetQ2_1: Q2.1 Q14.2 R40.2 R45.2 | length 238.4
  Bottom Layer w20: Q2.1@6138.76,1004.78 Q2.1@6139.29,1004.25 R45.2@6139.29,905.97 6137.78,904.47 R40.2@6137.78,832.61 6137.78,832.47 6138.29,832.97 Q14.2@6202.78,832.97
NetQ3_1: Q3.1 Q13.2 R38.2 R44.2 | length 236.4
  Bottom Layer w20: Q3.1@5690,1005 5690,909.41 5693.44,905.97 5692.93,905.47 R38.2@5692.93,829.47 ; R38.2@5696.44,832.97 Q13.2@5755.69,832.97
NetQ5_1: Q5.1 R54.1 R60.1 | length 251
  Bottom Layer w25: R54.1@5863.05,3608.89 5906.6,3565.34 Q5.1@5906.6,3494.47 5985.25,3573.12 R60.1@5985.25,3580.41
NetQ7_1: Q7.1 R57.1 R61.2 | length 248.1
  Bottom Layer w30: R57.1@5116.09,3603 5158.88,3560.21 Q7.1@5158.88,3492.68 5236.84,3570.65 R61.2@5236.84,3580.41
NetQ10_1: Q10.1 R5.1 R14.2 | length 212.4
  Bottom Layer w30: Q10.1@3511,3536.94 3511,3422.63 R5.1@3511.63,3422 3511,3421.37 3511,3341.09 3511,3328.09 R14.2@3512.09,3327
  Bottom Layer w40: R14.2@3511,3341.09 R14.2@3512.09,3340
NetR1_2: R1.2 U6.3 | length 61
  Bottom Layer w20: R1.2@6807.54,1215.74 6809.11,1217.31 U6.3@6867.88,1217.31
NetR10_1: R10.1 R22.2 | length 102.1
  Bottom Layer w40: R10.1@1939.83,336.76 R10.1@1939.91,336.85 ; R10.1@1942.91,337 1940.06,337 1943,339.94 R22.2@1943,434.91
NetR10_2: R10.2 U2.1 | length 5233.8
  Top Layer w20: v1(5530.94,671) v1(5961,671)
  Bottom Layer w20: R10.2@2057.09,337 2057.09,128.6 2149.54,36.14 4113.59,36.14 4256.8,179.35 5039.3,179.35 v1(5530.94,671) ; v1@5960.55,671 5960.55,635.99 6002.16,594.38 6360.18,594.38 6377.95,612.14 6377.95,749.21 6386.96,758.22 6386.96,790.95 6477.97,881.96 U2.1@6477.97,913.93
NetR11_2: R11.2 R77.1 | length 95.9
  Bottom Layer w40: R77.1@1472,646.09 1472.09,646 R11.2@1567.91,646
NetR15_1: R15.1 U1.5 | length 225.8
  Bottom Layer w20: U1.5@3039.94,717.9 3046.68,724.63 R15.1@3263,724.63
NetR16_1: R16.1 U1.7 | length 241.1
  Bottom Layer w20: R16.1@2737,665.63 2737.1,665.53 2915.68,665.53 2939.94,689.78 U1.7@2939.94,717.9
NetR17_1: R17.1 R47.2 U6.1 | length 203
  Bottom Layer w20: R17.1@6950,1712.5 6949.5,1712 R47.2@6949.5,1572 6949.5,1535.7 U6.1@6967.88,1517.31
NetR20_1: R20.1 R27.2 | length 422.9
  Bottom Layer w30: R27.2@2878.72,3312.87 3168.09,3023.49 R20.1@3181.79,3023.49
NetR21_1: R21.1 R33.2 | length 90.6
  Bottom Layer w40: R21.1@3191.96,1897.66 R33.2@3191.96,1988.31
NetR21_2: R21.2 R23.1 | length 87.2
  Bottom Layer w40: R21.2@3191.96,1817.66 3192.54,1817.08 R23.1@3192.54,1730.72
NetR22_1: R22.1 R31.2 | length 105.1
  Bottom Layer w40: R31.2@1838,548.91 1942.83,548.91 R22.1@1943,549.09
NetR27_1: R27.1 R34.2 | length 85
  Bottom Layer w40: R27.1@2798.83,3312.98 R34.2@2798.83,3397.96
NetR29_2: R29.2 R36.1 | length 97.4
  Bottom Layer w40: R36.1@5638.09,1768 5733.91,1768 R29.2@5735,1769.09
NetR36_2: R36.2 R43.1 | length 89.8
  Bottom Layer w40: R43.1@5434.09,1768 R36.2@5523.91,1768
NetR37_1: R37.1 R41.1 U3.9 | length 124.9
  Bottom Layer w20: U3.9@2315.78,3025.93 U3.9@2315.54,3026.17 2315.54,2968.92 R41.1@2315.81,2968.64 2315.81,2902.69 R37.1@2316.5,2902
NetR39_2: R39.2 R62.2 U3.4 | length 676.3
  Top Layer w20: v1(2320.96,3512.64) 2599.58,3234.02 v1(2647.98,3234.02)
  Bottom Layer w20: R62.2@2320.51,3625.24 2320.96,3624.8 R39.2@2320.96,3562.07 v1(2320.96,3512.64) ; U3.4@2530.1,3226.17 2590.71,3226.17 2598.56,3234.02 v1(2647.98,3234.02)
NetR46_2: R46.2 R86.1 | length 81.9
  Bottom Layer w20: R46.2@2803.32,2959.85 2883.94,2959.85 R86.1@2884.83,2958.96
NetR51_2: R51.2 R55.2 U4.3 | length 125.4
  Bottom Layer w20: U4.3@4117.28,3698 4171.5,3698 R55.2@4178,3691.5 R51.2@4240,3691.5
NetR63_2: R63.2 U9.3 | length 187.3
  Bottom Layer w20: U9.3@6407.32,2009.36 6407.32,2042.55 6425.27,2060.5 R63.2@6554,2060.5
NetR64_2: R64.2 U9.4 | length 65.2
  Bottom Layer w20: R64.2@6342.6,2118.89 6343.87,2117.63 U9.4@6407.32,2117.63
NetR67_1: R67.1 R68.1 R72.2 U11.3 | length 327.8
  Bottom Layer w20: R67.1@6355.81,1825.82 6381.99,1799.63 U11.3@6425.42,1799.63 6425.42,1833.09 6436.83,1844.5 R68.1@6569,1844.5 6569,1782.5 R72.2@6571.5,1780
NetR67_2: R67.2 R73.1 U11.4 U12.2 | length 1171.8
  Top Layer w23: v1(6355.81,1930.42) 6355.81,1813.81 6459.82,1709.79 6759.77,1709.79 6859.61,1609.95 7025.84,1609.95 7078.98,1556.81 U12.2@7078.98,1517.31
  Bottom Layer w20: R67.2@6355.81,1888.81 6406.33,1888.81 U11.4@6425.42,1907.9
  Bottom Layer w23: R67.2@6355.81,1888.81 v1(6355.81,1930.42) ; U12.2@7078.98,1517.31 7078.98,1559.48 R73.1@7096.5,1577
NetR69_1: R69.1 U11.1 | length 325.8
  Bottom Layer w20: U11.1@6500.22,1799.63 6500.22,1758.64 6522.23,1736.63 6697.34,1736.63 6718.84,1758.13 R69.1@6718.84,1806.33
NetR70_1: R70.1 U12.4 | length 83
  Bottom Layer w23: R70.1@7178.95,1134.31 U12.4@7178.98,1217.31
NetR71_1: R71.1 R73.2 U12.1 | length 418.2
  Top Layer w23: v1(6883.42,1649.82) 7046.47,1649.82 U12.1@7178.98,1517.31
  Bottom Layer w23: R73.2@7159.5,1577 7178.98,1557.52 U12.1@7178.98,1517.31
NetR86_2: R86.2 R87.1 | length 281.2
  Bottom Layer w25: 2972.06,2804.55 2964.83,2811.78 R86.2@2964.83,2958.96 R86.2@2972.85,2950.94 ; 2972.85,2803.76 R87.1@3052.4,2724.21
NetR89_2: R89.2 U3.3 | length 81.3
  Bottom Layer w20: U3.3@2530.1,3276.17 2580.43,3276.17 R89.2@2602.32,3298.06
PGND: C3.2 C7.2 C8.2 C15.2 C16.2 C17.1 C18.2 C19.2 C20.2 C21.2 C22.2 C23.2 C24.2 C25.2 C29.2 C30.2 C31.2 C32.2 C33.2 C34.2 C35.2 C36.2 C37.2 C38.2 C41.2 C43.2 C55.2 C56.2 C57.2 C58.2 C59.2 C69.2 D15.2 D16.2 D20.2 HS2.1 HS2.2 L1.3 L6.3 Q1.3 Q2.3 Q10.3 Q12.3 Q14.3 R1.1 R2.1 R3.1 R6.1 R7.1 R8.1 R12.1 R14.1 R19.1 R32.1 R35.1 R37.2 R45.1 R62.1 R76.1 R88.1 R89.1 R90.1 RT1.1 T1.7 TP1.1 TP3.1 U1.3 U2.11 U3.6 U3.13 U12.3 U13.2 | length 4269.1
  Top Layer w20: v1(6266,795) 6325.62,795 6546.38,574.24 6708,574.24 6739.65,605.89 6739.65,642.21 v1(6727.5,654.36)
  Bottom Layer w20: C21.2@1577,359.5 v1(1577,404.41) ; U13.2@1640.48,259.23 v1(1694.42,259.23) ; v1(1640.69,154.55) 1641.24,154 C7.2@1685.5,154 ; v1(2119.7,3372.69) C24.2@2163.43,3372.69 ; v1(2161.83,3004.81) C29.2@2161.83,3035.62 ; v1(2200.37,3232.63) C30.2@2245.41,3232.63 2251.88,3226.17 U3.13@2315.54,3226.17 ; R37.2@2253.5,2902 2253.5,2864.27 v1(2253.79,2863.98) ; C38.2@2446.67,3436.5 2446.67,3467.75 C37.2@2446.67,3499.14 ; U3.6@2530.1,3126.17 2570.15,3126.17 v1(2581.6,3114.73) ; v1(2664.81,2945.79) C43.2@2664.81,2977.04 ; R35.1@2665.14,3425.09 v1(2696.39,3425.09) ; C25.2@2665.22,3530.93 v1(2696.47,3530.93) ; R89.1@2665.31,3298.06 v1(2696.56,3298.06) ; C33.2@2665.31,3361.06 v1(2696.56,3361.06) ; C34.2@2726.91,3108.33 v1(2758.16,3108.33) ; v1(2728.62,2945.51) R90.1@2728.62,2976.76 ; C23.2@2817.94,866.18 v1(2857,866.18) 2953.63,866.18 v1(2989.94,902.49) ; 2831.04,3660.17 D16.2@2831.04,3788.33 ; Q12.3@2849.75,1061.85 2849.75,1088.12 C59.2@2901.63,1140 ; C58.2@2861.63,1207 2861.63,1180 C59.2@2901.63,1140 ; v1(2909.4,1103.69) 2909.4,1132.23 C59.2@2901.63,1140 ; U1.3@2989.94,932.46 v1(2989.94,965.4) ; R45.1@6202.28,905.97 6297.56,905.97 ; v1(6266,795) Q14.3@6297.84,795 ; Q14.3@6298.4,794.45 Q14.3@6297.84,795 ; Q2.3@6339.29,1004.25 6339.29,947.7 6297.56,905.97 ; v1@6726.53,654.36 v1(6727.5,654.36) ; C35.2@6727.84,557.09 C32.2@6727.84,620.01 6727.97,620.14 U2.11@6727.97,701.33 ; v2(6729.53,1088.01) 6800.4,1088.01 C19.2@6800.53,1087.89 ; C31.2@6850.46,566.28 R32.1@6914.46,566.28 v1(6944.39,566.28) v1@6946.2,568.09 ; R3.1@6868.25,1086.98 6868.78,1087.52 6904.53,1087.52 ; C20.2@6886.38,912.54 v1(6917.95,912.54) R12.1@6949.52,912.54 ; C22.2@7013.5,976 v1(7042.39,976) ; C29.2@2161.83,3035.62 2161.34,3036.11 C29.2@2161.62,3036.39 2161.83,3036.18 C29.2@2161.83,3035.62 ; 6297.56,905.97 6297.56,795.85 Q14.3@6297.27,795.57 Q14.3@6297.84,795
  Bottom Layer w25: C69.2@2503.66,802.49 v1@2541.81,802.49 ; C41.2@2590.59,2905.14 2590.59,2936.08 R88.1@2590.59,2967.14 ; C36.2@2816.35,3117.62 v1@2851.44,3117.62 ; C15.2@3786.64,814.56 v1@3824.8,814.56
  Bottom Layer w35: 3367.78,3639.94 3403.4,3675.57 3642.78,3675.57 3659.32,3659.02 C55.2@3659.32,3648 3668.93,3657.61 3668.93,3860.78 3769.65,3961.5 C57.2@3880.32,3961.5 C56.2@3968,3961.5 4008.64,3920.86 D15.2@4008.64,3896.42
  Bottom Layer w40: R19.1@2730,951 2819.62,951 2849.75,981.13 Q12.3@2849.75,1061.85 ; R6.1@3182.76,951 3261.78,951 3301.76,990.98 Q1.3@3301.76,1061.85
  other v1: 2555.01,762.93 2595.01,762.93 3838,775 3878,775 2555.01,802.93 2595.01,802.93 3838,815 3878,815 2555.01,842.93 2595.01,842.93 3838,855 3878,855 2856.35,3117.62
  other v2: 6418.96,1082.02 6605,1096.5 6667,1096.5 6389.03,1112.44 6359.03,1142.44 6438,1152 6625,1155 6669.51,1155 6714.01,1155 6759,1155 6408.07,1182.43 6475.15,1204.2 6560.64,1218.55 6452.11,1226.9 6531,1249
